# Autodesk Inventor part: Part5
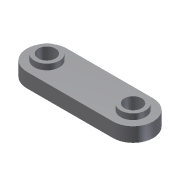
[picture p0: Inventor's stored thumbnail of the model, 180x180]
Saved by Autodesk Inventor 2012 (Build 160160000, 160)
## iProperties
Shininess: 77.0
Length Units: 11269
Angle Units: 11279
Time Units: 11290
Mass Units: 11283
Length Display Precision: 3
Angle Display Precision: 2
Created: 2002-01
Part Number: Part5
Document SubType Name: Modeling
Designer: ***
Density: 1 g/cm^3
Material: Default
Density: 0.0
Volumn: 0.0
Area: 0.0
PropertySet Name: Model Information
Control State: 0
Master: False
Checked Out: False
Author: ***
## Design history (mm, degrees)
sketch "Sketch1"
  geometry: L1 (-33.118, 12.346)-(26.882, 12.361); L2 (-33.111, -15.654)-(26.889, -15.639); C1 r 6 at (-33.114, -1.654); C2 r 6 at (26.886, -1.639); A1 r 14 centre (-33.114, -1.654) between (-33.118, 12.346) and (-33.111, -15.654); A2 r 14 centre (26.886, -1.639) between (26.889, -15.639) and (26.882, 12.361)
  constraints: 4 centre point, 4 end point, 4 point on circle, 4 tangent, 2 coincident, 2 equal radius
  dimensions: "d0" = 60 distance of L1.start L1.end; "d1" = 14 radius of A1; "d2" = 12 diameter of C1
extrude "Extrusion1" new body sketch "Sketch1" distance "d3" = 10; taper "d4" = 0 deg
sketch "Sketch2"
  geometry: C1 r 6 at (26.886, -1.639) reference; C2 r 6 at (-33.114, -1.654) reference; C3 r 8.694 at (-33.114, -1.654); C4 r 8.694 at (26.886, -1.639)
  constraints: 2 centre point, 2 coincident, 1 equal radius
extrude "Extrusion2" join sketch "Sketch2" distance "d5" = 4; taper "d6" = 0 deg
body "Solid1"
